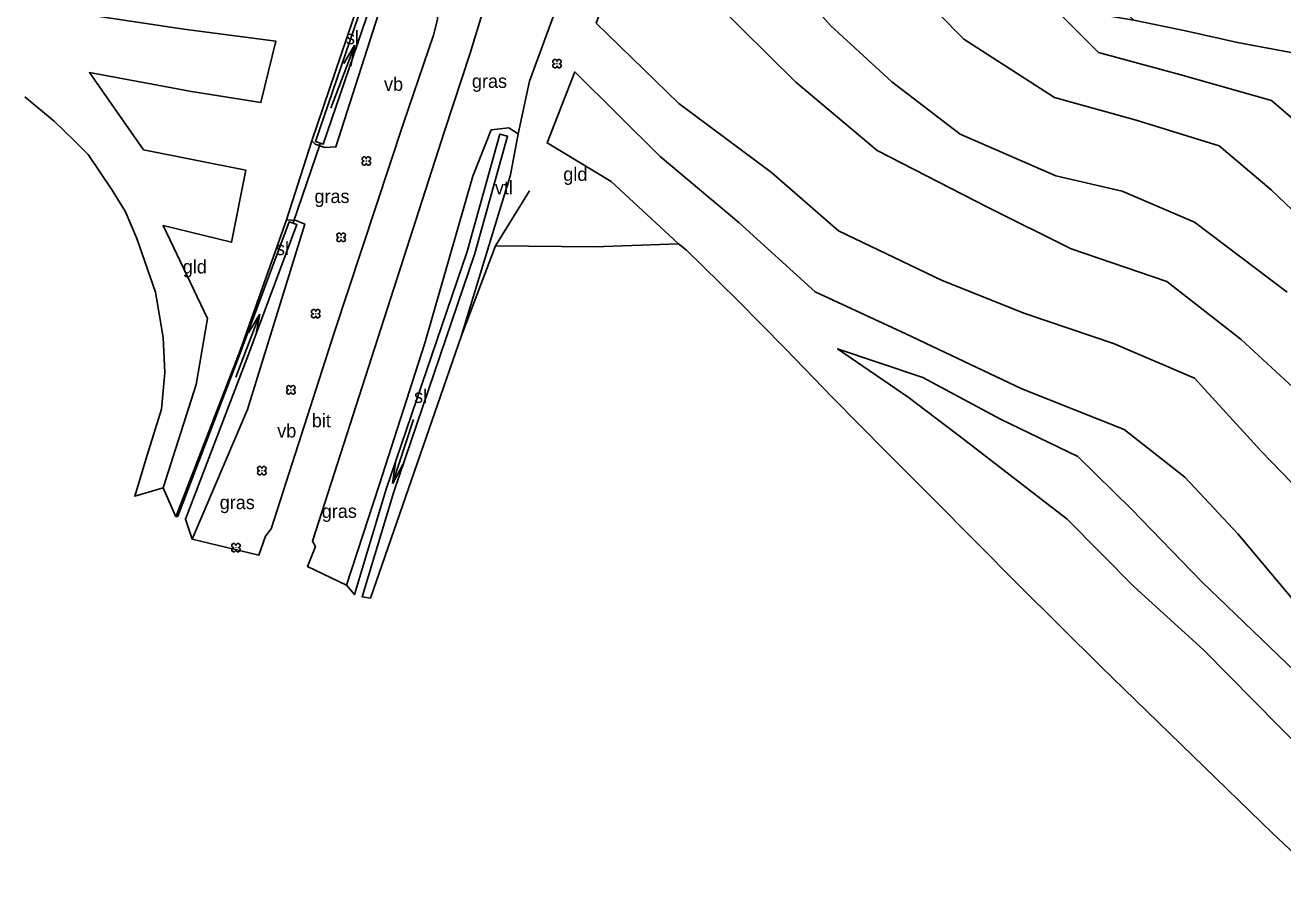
# Model space of a CAD drawing. Extents: x 154825 to 158680, y 370717 to 378075.
# Drawn here: x 155897.3 to 155990.5, y 376753 to 376817.5 of the extents above; entities that cross this region are included whole.
import ezdxf

# ---------------------------------------------------------------- set-up
doc = ezdxf.new("R2010")
doc.units = 0
for name, color, linetype in [('bitumenverharding(vs)', 7, 'Continuous'), ('boom', 7, 'Continuous'), ('duiker lijn', 7, 'Continuous'), ('grasland_productiegrasl(vs)', 7, 'Continuous'), ('grazige vegetatie(vs)', 7, 'Continuous'), ('hoogteverschillijn', 7, 'Continuous'), ('insteek sloot', 7, 'Continuous'), ('maaiveldlijn algemeen', 7, 'Continuous'), ('maaiveldlijn algemeen - gesloten verharding', 7, 'Continuous'), ('Sloot bodem', 7, 'Continuous'), ('sloot(vs)', 7, 'Continuous'), ('stroomrichting  watergangen', 7, 'Continuous'), ('verkeersb_z kabel', 7, 'Continuous'), ('verklikker transportleiding', 7, 'Continuous'), ('vlak_Grasland', 7, 'Continuous'), ('vlak_Grazige_vegetatie', 7, 'Continuous')]:
    doc.layers.add(name, color=color, linetype=linetype)

msp = doc.modelspace()

# ---------------------------------------------------------------- linework, layer by layer
at = {"layer": 'boom'}
for centre in [(155936.712, 376814.62), (155922.574, 376807.402), (155920.709, 376801.739), (155918.823, 376796.083), (155916.983, 376790.434), (155914.827, 376784.442), (155912.906, 376778.734)]:
    msp.add_circle(centre, 0.006, dxfattribs=at)
for centre, start, end in [((155936.554, 376814.778), 357.07502, 272.92498), ((155936.87, 376814.778), 267.07502, 182.92498), ((155936.554, 376814.462), 87.07502, 2.92498), ((155936.87, 376814.462), 177.07502, 92.92498), ((155922.416, 376807.56), 357.07502, 272.92498), ((155922.416, 376807.244), 87.07502, 2.92498), ((155922.732, 376807.56), 267.07502, 182.92498), ((155922.732, 376807.244), 177.07502, 92.92498), ((155920.551, 376801.898), 357.07502, 272.92498), ((155920.551, 376801.581), 87.07502, 2.92498), ((155920.867, 376801.898), 267.07502, 182.92498), ((155920.867, 376801.581), 177.07502, 92.92498), ((155918.665, 376796.241), 357.07502, 272.92498), ((155918.665, 376795.925), 87.07502, 2.92498), ((155918.981, 376796.241), 267.07502, 182.92498), ((155918.981, 376795.925), 177.07502, 92.92498), ((155916.825, 376790.592), 357.07502, 272.92498), ((155917.141, 376790.592), 267.07502, 182.92498), ((155916.825, 376790.276), 87.07502, 2.92498), ((155917.141, 376790.276), 177.07502, 92.92498), ((155914.669, 376784.6), 357.07502, 272.92498), ((155914.669, 376784.284), 87.07502, 2.92498), ((155914.985, 376784.6), 267.07502, 182.92498), ((155914.985, 376784.284), 177.07502, 92.92498), ((155912.748, 376778.892), 357.07502, 272.92498), ((155912.748, 376778.576), 87.07502, 2.92498), ((155913.065, 376778.892), 267.07502, 182.92498), ((155913.065, 376778.576), 177.07502, 92.92498)]:
    msp.add_arc(centre, 0.158, start, end, dxfattribs=at)
at = {"layer": 'duiker lijn'}
msp.add_lwpolyline([(155919.152, 376808.681), (155917.151, 376802.809)], dxfattribs=at)
at = {"layer": 'hoogteverschillijn'}
for points in [[(155991.54, 376815.37), (155987.15, 376816.19), (155983.3, 376817.06), (155979.48, 376817.84), (155977.78, 376819.42), (155975.13, 376822.26), (155970.74, 376826.8), (155967.74, 376829.82), (155963.85, 376833.97), (155958.6, 376839.3), (155952.8, 376845.56), (155950.02, 376848.51), (155948.11, 376850.44), (155946.71, 376847.26), (155951.01, 376842.68), (155953.78, 376839.71), (155956.93, 376836.2), (155963.97, 376828.38), (155967.35, 376824.5), (155971.64, 376820.68), (155976.86, 376815.44), (155982.97, 376813.8), (155989.69, 376811.89), (155993.57, 376808.55)], [(155994.4, 376800.74), (155989.65, 376805.26), (155985.81, 376808.54), (155979.65, 376810.44), (155973.59, 376812.11), (155966.88, 376816.43), (155961.26, 376822.16), (155956.57, 376827.35), (155952.32, 376830.93), (155945.66, 376837.42), (155943.37, 376830.22), (155948.43, 376825.65), (155952.39, 376822.65), (155956.98, 376817.44), (155961.53, 376813.27), (155966.61, 376809.39), (155973.68, 376806.3), (155978.62, 376805.16), (155983.98, 376802.87), (155990.83, 376797.67)], [(155993.54, 376788.54), (155987.44, 376794.17), (155981.92, 376798.48), (155974.82, 376800.89), (155968.62, 376803.98), (155960.44, 376808.18), (155954.42, 376813.24), (155948.36, 376819.22), (155942.2, 376824.67), (155939.62, 376817.62), (155945.74, 376811.67), (155952.61, 376806.55), (155957.57, 376802.23), (155965.26, 376798.55), (155971.4, 376796.09), (155977.96, 376793.86), (155983.98, 376791.3), (155988.91, 376785.9), (155994.12, 376780.51)], [(155892.77, 376819.62), (155901.63, 376818.3), (155909.05, 376817.18), (155915.86, 376816.29), (155914.76, 376811.73), (155909.61, 376812.55), (155902.04, 376813.96), (155906.06, 376808.23), (155913.64, 376806.73), (155912.58, 376801.38), (155907.51, 376802.62), (155910.8, 376795.72), (155909.95, 376790.82), (155907.52, 376783.18)], [(155991.43, 376774.69), (155987.18, 376779.75), (155983.26, 376783.96), (155978.76, 376787.49), (155971.16, 376790.51), (155962.58, 376794.59), (155955.86, 376797.7), (155950.18, 376802.84), (155944.35, 376807.73), (155938.02, 376814.01), (155935.98, 376808.75), (155940.73, 376805.88), (155945.72, 376801.27), (155939.49, 376801.04), (155932.16, 376801.12), (155934.67, 376805.19)], [(155905.41, 376782.55), (155906.33, 376785.59), (155907.38, 376789.01), (155907.64, 376791.71), (155907.51, 376794.32), (155906.94, 376797.69), (155905.56, 376801.67), (155904.73, 376803.63), (155903.74, 376805.24), (155901.95, 376807.88), (155900.95, 376808.89), (155899.45, 376810.33), (155897.26, 376812.15)], [(155946.32, 376800.8), (155950.05, 376797.13), (155953.65, 376793.47), (155957.13, 376789.87), (155961.15, 376785.81), (155964.55, 376782.41), (155970.97, 376775.93), (155977.04, 376769.92), (155983.86, 376763.3), (155989.75, 376757.57), (155994.63, 376752.99)], [(155994.58, 376761.2), (155990.26, 376765.47), (155984.64, 376771.17), (155979.49, 376775.83), (155974.54, 376780.85), (155966.94, 376786.71), (155962.75, 376789.9), (155957.51, 376793.48), (155963.83, 376791.35), (155969.58, 376788.26), (155975.32, 376785.49), (155979.31, 376781.6), (155984.52, 376776.2), (155992.67, 376768.37)]]:
    msp.add_lwpolyline(points, dxfattribs=at)
at = {"layer": 'insteek sloot'}
for points in [[(155922.41, 376820.35), (155922.793, 376820.353), (155923.641, 376820.13), (155923.9, 376819.644), (155920.317, 376808.448), (155919.501, 376808.407), (155918.792, 376808.654), (155918.527, 376808.892)], [(155918.527, 376808.892), (155922.41, 376820.35)], [(155933.83, 376809.418), (155933.146, 376809.871), (155931.841, 376809.712), (155930.47, 376806.283), (155926.907, 376793.901), (155923.533, 376783.359), (155921.105, 376775.95)], [(155933.83, 376809.418), (155933.255, 376806.372), (155929.6, 376794.385), (155922.875, 376774.989)], [(155916.644, 376803.038), (155913.214, 376793.341), (155908.454, 376781.026)], [(155916.644, 376803.038), (155917.367, 376802.996), (155918.015, 376802.728), (155913.756, 376788.987), (155909.66, 376779.374)]]:
    msp.add_lwpolyline(points, dxfattribs=at)
at = {"layer": 'maaiveldlijn algemeen'}
for points in [[(155938.088, 376824.783), (155936.865, 376819.298), (155934.67, 376813.332), (155933.83, 376809.418)], [(155916.644, 376803.038), (155918.527, 376808.892)]]:
    msp.add_lwpolyline(points, dxfattribs=at)
at = {"layer": 'maaiveldlijn algemeen - gesloten verharding'}
for points in [[(155933.641, 376826.476), (155930.262, 376815.394), (155928.376, 376809.621), (155923.203, 376793.574), (155918.573, 376779.226), (155918.797, 376778.825), (155918.219, 376777.336)], [(155927.76, 376819.579), (155927.858, 376817.889), (155927.55, 376816.743), (155925.323, 376810.209), (155920.199, 376794.655), (155915.514, 376780.124), (155915.103, 376779.586), (155914.606, 376778.187)]]:
    msp.add_lwpolyline(points, dxfattribs=at)
at = {"layer": 'Sloot bodem'}
for points in [[(155923.208, 376819.869), (155919.365, 376808.649), (155918.798, 376808.844), (155922.641, 376820.064), (155923.208, 376819.869)], [(155921.695, 376775.256), (155924.054, 376783.064), (155930.051, 376800.706), (155932.47, 376809.395), (155933.048, 376809.234), (155930.629, 376800.545), (155924.622, 376782.871), (155922.27, 376775.083)], [(155908.599, 376781.061), (155913.231, 376793.149), (155916.861, 376802.903), (155917.423, 376802.694), (155913.792, 376792.934), (155909.16, 376780.846)]]:
    msp.add_lwpolyline(points, dxfattribs=at)
at = {"layer": 'stroomrichting  watergangen'}
for p, q in [((155919.944, 376811.332), (155921.723, 376815.998)), ((155921.705, 376815.989), (155920.895, 376814.633)), ((155921.723, 376815.998), (155921.426, 376814.447)), ((155912.891, 376791.371), (155914.67, 376796.037)), ((155914.652, 376796.028), (155913.841, 376794.672)), ((155914.67, 376796.037), (155914.372, 376794.486)), ((155926.08, 376788.237), (155924.526, 376783.492)), ((155924.526, 376783.492), (155924.749, 376785.055)), ((155924.544, 376783.502), (155925.288, 376784.895))]:
    msp.add_line(p, q, dxfattribs=at)
at = {"layer": 'vlak_Grasland'}
for points in [[(155994.63, 376752.99), (155989.75, 376757.57), (155983.86, 376763.3), (155977.04, 376769.92), (155970.97, 376775.93), (155964.55, 376782.41), (155961.15, 376785.81), (155957.13, 376789.87), (155953.65, 376793.47), (155950.05, 376797.13), (155946.32, 376800.8), (155945.72, 376801.27), (155939.49, 376801.04), (155932.16, 376801.12), (155929.6, 376794.385), (155933.255, 376806.372), (155933.83, 376809.418), (155934.67, 376813.332), (155936.865, 376819.298), (155938.088, 376824.783), (155979.48, 376817.84), (155983.3, 376817.06), (155987.15, 376816.19), (155991.54, 376815.37)], [(155922.41, 376820.35), (155918.527, 376808.892), (155916.644, 376803.038), (155913.214, 376793.341), (155908.454, 376781.026), (155907.52, 376783.18), (155905.41, 376782.55), (155906.33, 376785.59), (155907.38, 376789.01), (155907.64, 376791.71), (155907.51, 376794.32), (155906.94, 376797.69), (155905.56, 376801.67), (155904.73, 376803.63), (155903.74, 376805.24), (155901.95, 376807.88), (155900.95, 376808.89), (155899.45, 376810.33), (155897.26, 376812.15)]]:
    msp.add_lwpolyline(points, dxfattribs=at)
at = {"layer": 'vlak_Grazige_vegetatie'}
for points in [[(155936.865, 376819.298), (155934.67, 376813.332), (155933.83, 376809.418), (155933.146, 376809.871), (155931.841, 376809.712), (155930.47, 376806.283), (155926.907, 376793.901), (155923.533, 376783.359), (155921.105, 376775.95), (155918.219, 376777.336), (155918.797, 376778.825), (155918.573, 376779.226), (155923.203, 376793.574), (155928.376, 376809.621), (155930.262, 376815.394), (155933.641, 376826.476)], [(155927.858, 376817.889), (155927.55, 376816.743), (155925.323, 376810.209), (155920.199, 376794.655), (155915.514, 376780.124), (155915.103, 376779.586), (155914.606, 376778.187), (155909.66, 376779.374), (155913.756, 376788.987), (155918.015, 376802.728), (155917.367, 376802.996), (155916.644, 376803.038), (155918.527, 376808.892), (155918.792, 376808.654), (155919.501, 376808.407), (155920.317, 376808.448), (155923.9, 376819.644)]]:
    msp.add_lwpolyline(points, dxfattribs=at)
for points in [[(155923.641, 376820.13), (155923.9, 376819.644), (155920.317, 376808.448), (155919.501, 376808.407), (155918.792, 376808.654), (155918.527, 376808.892), (155922.41, 376820.35), (155922.793, 376820.353)], [(155918.798, 376808.843), (155919.365, 376808.649), (155923.208, 376819.869), (155922.641, 376820.064)], [(155933.83, 376809.418), (155933.255, 376806.372), (155929.6, 376794.385), (155922.875, 376774.989), (155922.27, 376775.083), (155924.622, 376782.871), (155930.629, 376800.545), (155933.048, 376809.234), (155932.47, 376809.395), (155930.051, 376800.706), (155924.054, 376783.064), (155921.695, 376775.256), (155921.105, 376775.95), (155923.533, 376783.359), (155926.907, 376793.901), (155930.47, 376806.283), (155931.841, 376809.712), (155933.146, 376809.871)], [(155917.367, 376802.996), (155918.015, 376802.728), (155913.756, 376788.987), (155909.66, 376779.374), (155909.159, 376780.846), (155913.792, 376792.934), (155917.423, 376802.694), (155916.861, 376802.903), (155913.231, 376793.149), (155908.599, 376781.061), (155908.454, 376781.026), (155913.214, 376793.341), (155916.644, 376803.038)]]:
    msp.add_lwpolyline(points, close=True, dxfattribs=at)

# ---------------------------------------------------------------- texts
at = {"layer": 'bitumenverharding(vs)'}
msp.add_text('bit', height=1, dxfattribs=at).set_placement((155918.533, 376787.661))
at = {"layer": 'grasland_productiegrasl(vs)'}
for p in [(155937.178, 376805.93), (155908.967, 376799.066)]:
    msp.add_text('gld', height=1, dxfattribs=at).set_placement(p)
at = {"layer": 'grazige vegetatie(vs)'}
for p in [(155930.403, 376812.827), (155918.729, 376804.288), (155911.704, 376781.589), (155919.27, 376780.94)]:
    msp.add_text('gras', height=1, dxfattribs=at).set_placement(p)
at = {"layer": 'sloot(vs)'}
for p in [(155921.062, 376816.062), (155915.873, 376800.423), (155926.115, 376789.472)]:
    msp.add_text('sl', height=1, dxfattribs=at).set_placement(p)
at = {"layer": 'verkeersb_z kabel'}
for p in [(155923.888, 376812.606), (155915.971, 376786.901)]:
    msp.add_text('vb', height=1, dxfattribs=at).set_placement(p)
at = {"layer": 'verklikker transportleiding'}
msp.add_text('vtl', height=1, dxfattribs=at).set_placement((155932.103, 376804.931))

doc.saveas('drawing.dxf')
